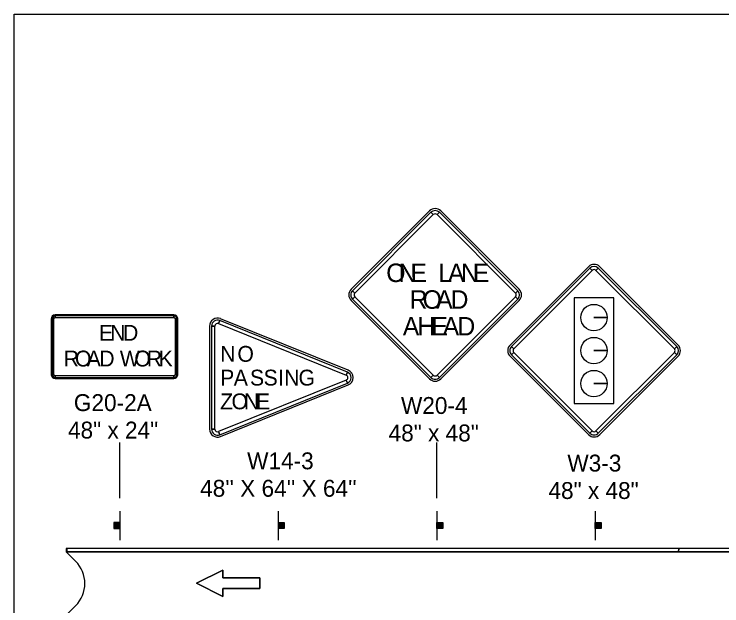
# Model space of a CAD drawing. Extents: x -2134934 to -2119606, y -2139046 to -2137036.
# Drawn here: x -2130232 to -2129562, y -2137596 to -2137036 of the extents above; entities that cross this region are included whole.
import ezdxf

# ---------------------------------------------------------------- set-up
doc = ezdxf.new("R2010")
doc.units = 0
for name, color, linetype in [('Default', 7, 'Continuous'), ('dsnStdLabel', 7, 'Continuous'), ('dsnStdLineWork', 7, 'Continuous'), ('Level 2', 7, 'Continuous')]:
    doc.layers.add(name, color=color, linetype=linetype)

msp = doc.modelspace()

# ---------------------------------------------------------------- linework, layer by layer
at = {"layer": 'Default'}
msp.add_lwpolyline([(-2130231.95, -2137035.95), (-2127096.96, -2137035.95), (-2127096.96, -2139045.94), (-2130231.95, -2139045.94)], close=True, dxfattribs=at)
at = {"layer": 'dsnStdLabel'}
for p, q in [((-2129838.72, -2137222.31), (-2129912.96, -2137296.56)), ((-2129837.39, -2137223.64), (-2129835.18, -2137225.85)), ((-2129831.65, -2137225.85), (-2129829.44, -2137223.64)), ((-2129753.86, -2137296.56), (-2129828.11, -2137222.31)), ((-2129688.28, -2137275.12), (-2129762.53, -2137349.37)), ((-2129686.96, -2137276.45), (-2129684.75, -2137278.66)), ((-2129681.21, -2137278.66), (-2129679, -2137276.45)), ((-2129603.43, -2137349.37), (-2129677.68, -2137275.12)), ((-2129909.43, -2137300.09), (-2129911.64, -2137297.88)), ((-2129755.19, -2137297.88), (-2129757.4, -2137300.09)), ((-2129912.96, -2137307.16), (-2129838.72, -2137381.41)), ((-2129911.64, -2137305.84), (-2129909.43, -2137303.63)), ((-2129828.11, -2137381.41), (-2129753.86, -2137307.16)), ((-2129757.4, -2137303.63), (-2129755.19, -2137305.84)), ((-2130080.67, -2137320.89), (-2130193.17, -2137320.89)), ((-2130193.17, -2137323.39), (-2130193.17, -2137321.82)), ((-2130080.67, -2137321.82), (-2130080.67, -2137323.39)), ((-2130196.92, -2137324.64), (-2130196.92, -2137377.14)), ((-2130195.99, -2137324.64), (-2130194.42, -2137324.64)), ((-2130079.42, -2137324.64), (-2130077.86, -2137324.64)), ((-2130076.92, -2137377.14), (-2130076.92, -2137324.64)), ((-2130038.48, -2137329.01), (-2130037.31, -2137326.11)), ((-2129915.78, -2137373.25), (-2130036.61, -2137324.37)), ((-2129670.57, -2137323.34), (-2129683.07, -2137323.34)), ((-2129683.07, -2137323.34), (-2129670.57, -2137323.34)), ((-2130046.92, -2137331.32), (-2130046.92, -2137429.07)), ((-2130045.04, -2137331.32), (-2130041.92, -2137331.32)), ((-2129758.99, -2137352.9), (-2129761.2, -2137350.69)), ((-2129670.57, -2137354.59), (-2129683.07, -2137354.59)), ((-2129683.07, -2137354.59), (-2129670.57, -2137354.59)), ((-2129604.76, -2137350.69), (-2129606.96, -2137352.9)), ((-2129762.53, -2137359.98), (-2129688.28, -2137434.22)), ((-2129761.2, -2137358.65), (-2129758.99, -2137356.44)), ((-2129677.68, -2137434.22), (-2129603.43, -2137359.98)), ((-2129606.96, -2137356.44), (-2129604.76, -2137358.65)), ((-2129916.48, -2137374.98), (-2129917.66, -2137377.88)), ((-2130194.42, -2137377.14), (-2130195.99, -2137377.14)), ((-2130193.17, -2137379.95), (-2130193.17, -2137378.39)), ((-2130193.17, -2137380.89), (-2130080.67, -2137380.89)), ((-2130080.67, -2137378.39), (-2130080.67, -2137379.95)), ((-2130077.86, -2137377.14), (-2130079.42, -2137377.14)), ((-2129835.18, -2137377.87), (-2129837.39, -2137380.08)), ((-2129829.44, -2137380.08), (-2129831.65, -2137377.87)), ((-2130036.61, -2137436.03), (-2129915.78, -2137387.15)), ((-2129917.66, -2137382.52), (-2129916.48, -2137385.41)), ((-2129670.57, -2137385.84), (-2129683.07, -2137385.84)), ((-2129683.07, -2137385.84), (-2129670.57, -2137385.84)), ((-2130041.92, -2137429.07), (-2130045.04, -2137429.07)), ((-2130037.31, -2137434.29), (-2130038.48, -2137431.39)), ((-2129684.75, -2137430.69), (-2129686.96, -2137432.9)), ((-2129679, -2137432.9), (-2129681.21, -2137430.69))]:
    msp.add_line(p, q, dxfattribs=at)
for points in [[(-2129837.39, -2137223.64), (-2129911.64, -2137297.88), (-2129909.43, -2137300.09), (-2129835.18, -2137225.85), (-2129837.39, -2137223.64)], [(-2129755.19, -2137297.88), (-2129829.44, -2137223.64), (-2129831.65, -2137225.85), (-2129757.4, -2137300.09), (-2129755.19, -2137297.88)], [(-2129686.96, -2137276.45), (-2129761.2, -2137350.69), (-2129758.99, -2137352.9), (-2129684.75, -2137278.66), (-2129686.96, -2137276.45)], [(-2129604.76, -2137350.69), (-2129679, -2137276.45), (-2129681.21, -2137278.66), (-2129606.96, -2137352.9), (-2129604.76, -2137350.69)], [(-2129911.64, -2137305.84), (-2129837.39, -2137380.08), (-2129835.18, -2137377.87), (-2129909.43, -2137303.63), (-2129911.64, -2137305.84)], [(-2129829.44, -2137380.08), (-2129755.19, -2137305.84), (-2129757.4, -2137303.63), (-2129831.65, -2137377.87), (-2129829.44, -2137380.08)], [(-2129664.25, -2137304.73), (-2129701.71, -2137304.73), (-2129701.71, -2137404.62), (-2129664.25, -2137404.62), (-2129664.25, -2137304.73)], [(-2130080.67, -2137321.82), (-2130193.17, -2137321.82), (-2130193.17, -2137323.39), (-2130080.67, -2137323.39), (-2130080.67, -2137321.82)], [(-2130195.99, -2137324.64), (-2130195.99, -2137377.14), (-2130194.42, -2137377.14), (-2130194.42, -2137324.64), (-2130195.99, -2137324.64)], [(-2130077.86, -2137377.14), (-2130077.86, -2137324.64), (-2130079.42, -2137324.64), (-2130079.42, -2137377.14), (-2130077.86, -2137377.14)], [(-2129916.48, -2137374.98), (-2130037.31, -2137326.11), (-2130038.48, -2137329.01), (-2129917.66, -2137377.88), (-2129916.48, -2137374.98)], [(-2130045.04, -2137331.32), (-2130045.04, -2137429.07), (-2130041.92, -2137429.07), (-2130041.92, -2137331.32), (-2130045.04, -2137331.32)], [(-2129761.2, -2137358.65), (-2129686.96, -2137432.9), (-2129684.75, -2137430.69), (-2129758.99, -2137356.44), (-2129761.2, -2137358.65)], [(-2129679, -2137432.9), (-2129604.76, -2137358.65), (-2129606.96, -2137356.44), (-2129681.21, -2137430.69), (-2129679, -2137432.9)], [(-2130193.17, -2137379.95), (-2130080.67, -2137379.95), (-2130080.67, -2137378.39), (-2130193.17, -2137378.39), (-2130193.17, -2137379.95)], [(-2130037.31, -2137434.29), (-2129916.48, -2137385.41), (-2129917.66, -2137382.52), (-2130038.48, -2137431.39), (-2130037.31, -2137434.29)]]:
    msp.add_lwpolyline(points, close=True, dxfattribs=at)
for centre in [(-2129683.07, -2137323.34), (-2129683.07, -2137354.59), (-2129683.07, -2137385.84)]:
    msp.add_circle(centre, 12.5, dxfattribs=at)
for centre, radius, start, end in [((-2129833.41, -2137227.61), 7.5, 44.99999, 134.99974), ((-2129833.41, -2137227.61), 5.62, 44.99999, 134.99974), ((-2129833.41, -2137227.61), 2.5, 44.99999, 134.99974), ((-2129682.98, -2137280.43), 7.5, 44.99999, 134.99974), ((-2129682.98, -2137280.43), 5.62, 44.99999, 134.99974), ((-2129682.98, -2137280.43), 2.5, 44.99999, 134.99974), ((-2129907.66, -2137301.86), 7.5, 134.99974, 224.99995), ((-2129907.66, -2137301.86), 5.62, 134.99974, 224.99995), ((-2129907.66, -2137301.86), 2.5, 134.99974, 224.99995), ((-2129759.17, -2137301.86), 2.5, 315.00016, 44.9998), ((-2129759.17, -2137301.86), 5.62, 315.00016, 44.9998), ((-2129759.17, -2137301.86), 7.5, 315.00016, 44.9998), ((-2130193.17, -2137324.64), 3.75, 90.00021, 179.99985), ((-2130193.17, -2137324.64), 2.81, 90.00021, 179.99985), ((-2130080.67, -2137324.64), 3.75, 0, 90.00021), ((-2130080.67, -2137324.64), 2.81, 0, 90.00021), ((-2130193.17, -2137324.64), 1.25, 90.00021, 179.99985), ((-2130080.67, -2137324.64), 1.25, 0, 90.00021), ((-2130039.42, -2137331.32), 7.5, 67.97571, 179.99985), ((-2130039.42, -2137331.32), 5.62, 67.97571, 179.99985), ((-2130039.42, -2137331.32), 2.5, 67.97571, 179.99985), ((-2129757.23, -2137354.67), 7.5, 134.99974, 224.99995), ((-2129757.23, -2137354.67), 5.62, 134.99974, 224.99995), ((-2129757.23, -2137354.67), 2.5, 134.99974, 224.99995), ((-2129608.73, -2137354.67), 2.5, 315.00016, 44.9998), ((-2129608.73, -2137354.67), 5.62, 315.00016, 44.9998), ((-2129608.73, -2137354.67), 7.5, 315.00016, 44.9998), ((-2129918.59, -2137380.2), 5.62, 292.02456, 67.97541), ((-2129918.59, -2137380.2), 7.5, 292.02456, 67.97598), ((-2130193.17, -2137377.14), 3.75, 179.99985, 270.00006), ((-2130193.17, -2137377.14), 2.81, 179.99985, 270.00006), ((-2130193.17, -2137377.14), 1.25, 179.99985, 270.00006), ((-2130080.67, -2137377.14), 3.75, 270.00006, 0.00027), ((-2130080.67, -2137377.14), 2.81, 270.00006, 0.00027), ((-2130080.67, -2137377.14), 1.25, 270.00006, 0.00027), ((-2129918.59, -2137380.2), 2.5, 292.02456, 67.97541), ((-2129833.41, -2137376.11), 7.5, 224.99995, 315.00016), ((-2129833.41, -2137376.11), 5.62, 224.99995, 315.00016), ((-2129833.41, -2137376.11), 2.5, 224.99995, 315.00016), ((-2130039.42, -2137429.07), 7.5, 179.99985, 292.02456), ((-2130039.42, -2137429.07), 5.62, 179.99985, 292.02456), ((-2130039.42, -2137429.07), 2.5, 179.99985, 292.02456), ((-2129682.98, -2137428.92), 7.5, 224.99995, 315.00016), ((-2129682.98, -2137428.92), 5.62, 224.99995, 315.00016), ((-2129682.98, -2137428.92), 2.5, 224.99995, 315.00016)]:
    msp.add_arc(centre, radius, start, end, dxfattribs=at)
at = {"layer": 'dsnStdLineWork'}
for p, q in [((-2128680.12, -2137542.16), (-2130182.57, -2137542.16)), ((-2130182.57, -2137542.16), (-2130182.57, -2137545.16)), ((-2129602.5, -2137542.16), (-2130182.57, -2137542.16)), ((-2130181.95, -2137542.16), (-2130181.95, -2137545.16)), ((-2129602.5, -2137542.16), (-2129603.51, -2137545.16)), ((-2129603.51, -2137545.16), (-2129602.5, -2137542.16)), ((-2129329.62, -2137542.16), (-2129602.5, -2137542.16)), ((-2128680.12, -2137545.16), (-2130182.57, -2137545.16)), ((-2130182.57, -2137545.16), (-2129603.51, -2137545.16)), ((-2129603.51, -2137545.16), (-2129329.62, -2137545.16))]:
    msp.add_line(p, q, dxfattribs=at)
msp.add_lwpolyline([(-2130182.37, -2137545.16), (-2128872.37, -2137545.16)], dxfattribs=at)
at = {"layer": 'Level 2'}
for p, q in [((-2130131.95, -2137494.5), (-2130131.95, -2137441.62)), ((-2129831.95, -2137494.5), (-2129831.95, -2137441.62)), ((-2130131.95, -2137506.66), (-2130131.95, -2137534.16)), ((-2129981.95, -2137506.66), (-2129981.95, -2137534.16)), ((-2129831.95, -2137506.66), (-2129831.95, -2137534.16)), ((-2129681.95, -2137506.66), (-2129681.95, -2137534.16)), ((-2130137.28, -2137517.52), (-2130137.28, -2137523.11)), ((-2130136.96, -2137523.11), (-2130136.96, -2137517.52)), ((-2130136.73, -2137517.52), (-2130136.73, -2137523.11)), ((-2130136.41, -2137523.11), (-2130136.41, -2137517.52)), ((-2130136.19, -2137517.52), (-2130136.21, -2137523.11)), ((-2130135.78, -2137523.11), (-2130135.76, -2137517.52)), ((-2130135.55, -2137517.52), (-2130135.55, -2137523.11)), ((-2130135.12, -2137523.11), (-2130135.12, -2137517.52)), ((-2130134.75, -2137517.52), (-2130134.75, -2137523.11)), ((-2130134.43, -2137523.11), (-2130134.41, -2137517.52)), ((-2130134.2, -2137517.52), (-2130134.2, -2137523.11)), ((-2130133.94, -2137523.11), (-2130133.94, -2137517.52)), ((-2130133.6, -2137517.52), (-2130133.6, -2137523.11)), ((-2130133.4, -2137523.11), (-2130133.4, -2137517.52)), ((-2130133.17, -2137517.52), (-2130133.17, -2137523.11)), ((-2130132.91, -2137523.11), (-2130132.91, -2137517.52)), ((-2130132.65, -2137517.52), (-2130132.65, -2137523.11)), ((-2130132.36, -2137523.11), (-2130132.36, -2137517.52)), ((-2129981.54, -2137523.11), (-2129981.54, -2137517.52)), ((-2129981.26, -2137517.52), (-2129981.26, -2137523.11)), ((-2129980.99, -2137523.11), (-2129980.99, -2137517.52)), ((-2129980.73, -2137517.52), (-2129980.73, -2137523.11)), ((-2129980.51, -2137523.11), (-2129980.51, -2137517.52)), ((-2129980.3, -2137517.52), (-2129980.3, -2137523.11)), ((-2129979.96, -2137523.11), (-2129979.96, -2137517.52)), ((-2129979.7, -2137517.52), (-2129979.7, -2137523.11)), ((-2129979.47, -2137523.11), (-2129979.49, -2137517.52)), ((-2129979.16, -2137517.52), (-2129979.16, -2137523.11)), ((-2129978.78, -2137523.11), (-2129978.78, -2137517.52)), ((-2129978.35, -2137517.52), (-2129978.35, -2137523.11)), ((-2129978.12, -2137523.11), (-2129978.14, -2137517.52)), ((-2129977.71, -2137517.52), (-2129977.69, -2137523.11)), ((-2129977.49, -2137523.11), (-2129977.49, -2137517.52)), ((-2129977.17, -2137517.52), (-2129977.17, -2137523.11)), ((-2129976.94, -2137523.11), (-2129976.94, -2137517.52)), ((-2129976.62, -2137517.52), (-2129976.62, -2137523.11)), ((-2129831.54, -2137523.11), (-2129831.54, -2137517.52)), ((-2129831.26, -2137517.52), (-2129831.26, -2137523.11)), ((-2129830.99, -2137523.11), (-2129830.99, -2137517.52)), ((-2129830.73, -2137517.52), (-2129830.73, -2137523.11)), ((-2129830.51, -2137523.11), (-2129830.51, -2137517.52)), ((-2129830.3, -2137517.52), (-2129830.3, -2137523.11)), ((-2129829.96, -2137523.11), (-2129829.96, -2137517.52)), ((-2129829.7, -2137517.52), (-2129829.7, -2137523.11)), ((-2129829.47, -2137523.11), (-2129829.49, -2137517.52)), ((-2129829.16, -2137517.52), (-2129829.16, -2137523.11)), ((-2129828.78, -2137523.11), (-2129828.78, -2137517.52)), ((-2129828.35, -2137517.52), (-2129828.35, -2137523.11)), ((-2129828.12, -2137523.11), (-2129828.14, -2137517.52)), ((-2129827.71, -2137517.52), (-2129827.69, -2137523.11)), ((-2129827.49, -2137523.11), (-2129827.49, -2137517.52)), ((-2129827.17, -2137517.52), (-2129827.17, -2137523.11)), ((-2129826.94, -2137523.11), (-2129826.94, -2137517.52)), ((-2129826.62, -2137517.52), (-2129826.62, -2137523.11)), ((-2129681.54, -2137523.11), (-2129681.54, -2137517.52)), ((-2129681.26, -2137517.52), (-2129681.26, -2137523.11)), ((-2129680.99, -2137523.11), (-2129680.99, -2137517.52)), ((-2129680.73, -2137517.52), (-2129680.73, -2137523.11)), ((-2129680.51, -2137523.11), (-2129680.51, -2137517.52)), ((-2129680.3, -2137517.52), (-2129680.3, -2137523.11)), ((-2129679.96, -2137523.11), (-2129679.96, -2137517.52)), ((-2129679.7, -2137517.52), (-2129679.7, -2137523.11)), ((-2129679.48, -2137523.11), (-2129679.49, -2137517.52)), ((-2129679.16, -2137517.52), (-2129679.16, -2137523.11)), ((-2129678.78, -2137523.11), (-2129678.78, -2137517.52)), ((-2129678.35, -2137517.52), (-2129678.35, -2137523.11)), ((-2129678.13, -2137523.11), (-2129678.14, -2137517.52)), ((-2129677.71, -2137517.52), (-2129677.69, -2137523.11)), ((-2129677.49, -2137523.11), (-2129677.49, -2137517.52)), ((-2129677.17, -2137517.52), (-2129677.17, -2137523.11)), ((-2129676.94, -2137523.11), (-2129676.94, -2137517.52)), ((-2129676.63, -2137517.52), (-2129676.63, -2137523.11)), ((-2130182.57, -2137545.16), (-2130173.79, -2137553.95)), ((-2128680.12, -2137545.16), (-2130182.57, -2137545.16)), ((-2130182.57, -2137545.16), (-2130173.78, -2137553.95)), ((-2130173.78, -2137596.37), (-2130191.36, -2137613.95))]:
    msp.add_line(p, q, dxfattribs=at)
for points in [[(-2130132.05, -2137523.11), (-2130132.05, -2137517.48), (-2130137.67, -2137517.48), (-2130137.67, -2137523.11)], [(-2129981.86, -2137523.11), (-2129981.86, -2137517.48), (-2129976.23, -2137517.48), (-2129976.23, -2137523.11)], [(-2129831.86, -2137523.11), (-2129831.86, -2137517.48), (-2129826.23, -2137517.48), (-2129826.23, -2137523.11)], [(-2129681.86, -2137523.11), (-2129681.86, -2137517.48), (-2129676.23, -2137517.48), (-2129676.23, -2137523.11)], [(-2129999.3, -2137579.99), (-2129999.3, -2137569.99), (-2130034.3, -2137569.99), (-2130034.3, -2137562.49), (-2130059.3, -2137574.99), (-2130034.3, -2137587.49), (-2130034.3, -2137579.99)]]:
    msp.add_lwpolyline(points, close=True, dxfattribs=at)
msp.add_lwpolyline([(-2130034.3, -2137579.99), (-2130034.3, -2137587.49), (-2130059.3, -2137574.99), (-2130034.3, -2137562.49), (-2130034.3, -2137569.99), (-2129999.3, -2137569.99), (-2129999.3, -2137579.99), (-2130034.3, -2137579.99)], dxfattribs=at)
msp.add_arc((-2130195, -2137575.16), 30, 315, 45, dxfattribs=at)
msp.add_arc((-2130195, -2137575.16), 30, 315, 45, dxfattribs=at)

# ---------------------------------------------------------------- texts
at = {"layer": 'dsnStdLabel'}
for s, height, p in [('O', 17.5, (-2129879.7, -2137289.67)), ('N', 17.5, (-2129867.92, -2137289.67)), ('E', 17.5, (-2129856.7, -2137289.67)), ('L', 17.5, (-2129830.45, -2137289.67)), ('A', 17.5, (-2129821.25, -2137289.67)), ('N', 17.5, (-2129808.98, -2137289.67)), ('E', 17.5, (-2129797.75, -2137289.67)), ('R', 17.5, (-2129857.59, -2137314.98)), ('O', 17.5, (-2129845.3, -2137314.98)), ('A', 17.5, (-2129832.46, -2137314.98)), ('D', 17.5, (-2129818.81, -2137314.98)), ('A', 17.5, (-2129864.03, -2137340.3)), ('H', 17.5, (-2129850.16, -2137340.3)), ('E', 17.5, (-2129836.95, -2137340.3)), ('A', 17.5, (-2129826.23, -2137340.3)), ('D', 17.5, (-2129812.37, -2137340.3)), ('E', 15, (-2130151.6, -2137345.26)), ('N', 15, (-2130140.98, -2137345.26)), ('D', 15, (-2130128.89, -2137345.26)), ('R', 15, (-2130185.06, -2137369.64)), ('O', 15, (-2130174.38, -2137369.64)), ('A', 15, (-2130163.22, -2137369.64)), ('D', 15, (-2130151.36, -2137369.64)), ('W', 15, (-2130131.91, -2137369.64)), ('O', 15, (-2130118.18, -2137369.64)), ('R', 15, (-2130106.41, -2137369.64)), ('K', 15, (-2130095.11, -2137369.64)), ('N', 15, (-2130036.95, -2137365.2)), ('O', 15, (-2130020.61, -2137365.2)), ('P', 15, (-2130036.95, -2137387.7)), ('A', 15, (-2130024.06, -2137387.7)), ('S', 15, (-2130008.71, -2137387.7)), ('S', 15, (-2129995.82, -2137387.7)), ('I', 15, (-2129982.22, -2137387.7)), ('N', 15, (-2129976.36, -2137387.7)), ('G', 15, (-2129962.77, -2137387.7)), ('Z', 15, (-2130036.95, -2137410.2)), ('O', 15, (-2130026.21, -2137410.2)), ('N', 15, (-2130014.38, -2137410.2)), ('E', 15, (-2130003.02, -2137410.2)), ('G20-2A', 16, (-2130175.45, -2137411.89)), ('W20-4', 16, (-2129865.78, -2137414.61)), ('48" x 24"', 16, (-2130180.99, -2137437.89)), ('48" x 48"', 16, (-2129877.48, -2137440.61)), ('W14-3', 16, (-2130011.41, -2137467.03)), ('W3-3', 16, (-2129708.27, -2137469.14)), ("48'' X 64'' X 64''", 16, (-2130055.9, -2137493.03)), ('48" x 48"', 16, (-2129726.15, -2137495.14))]:
    msp.add_text(s, height=height, dxfattribs=at).set_placement(p)

doc.saveas('drawing.dxf')
